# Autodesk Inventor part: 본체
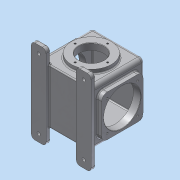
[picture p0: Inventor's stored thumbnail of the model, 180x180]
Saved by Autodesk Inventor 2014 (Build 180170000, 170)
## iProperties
Created: 2026-01
Part Number: 본체
Material: 알루미늄 6061
Document SubType Name: Modeling
Designer: dg
Mass: 2717.81 g
Surface Area: 2456.08 cm^2
Volume: 1002.88 cm^3
Density: 2.71 g/cm^3
Appearance: 알루미늄 - 평지
Author: dg
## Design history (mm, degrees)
sketch "스케치1"
  geometry: L1 (-71, 74)-(71, 74); L2 (71, 74)-(71, -74); L3 (71, -74)-(-71, -74); L4 (-71, -74)-(-71, 74); 3 further points
  constraints: 8 end point, 2 midpoint, 2 parallel, 1 horizontal, 1 horizontal alignment, 1 perpendicular, 1 vertical alignment
  dimensions: "d0" = 148 distance of L1.end L2.end; "d1" = 142 distance of L1.start L1.end
extrude "돌출1" new body sketch "스케치1" distance "d2" = 148; taper "d3" = 0 deg
fillet "모깎기1" dims "d7" = 10
fillet "모깎기2" dims "d8" = 10
feature "쉘2" dims "d82" = 7
sketch "스케치12"
  geometry: C1 r 54 at (0, 0); 1 further point
  constraints: 1 centre point, 1 coincident
  dimensions: "d79" = 108 diameter of C1
extrude "돌출8" join sketch "스케치12" distance "d80" = 11; taper "d81" = 0 deg
sketch "스케치13"
  geometry: L1 (0, 138)-(128, 138) reference; L2 (8, 130)-(120, 130); L3 (120, 130)-(120, 18); L4 (120, 18)-(8, 18); L5 (8, 18)-(8, 130); L6 (-21, 128)-(-21, 20) reference; 5 further points
  constraints: 8 end point, 4 midpoint, 2 parallel, 2 perpendicular, 1 horizontal, 1 horizontal alignment, 1 vertical alignment
  dimensions: "d83" = 112 distance of L2.start L2.end
extrude "돌출9" join sketch "스케치13" distance "d84" = 13; taper "d85" = 0 deg
fillet "모깎기9" dims "d86" = 15
sketch "스케치14"
  geometry: L1 (105, 130)-(23, 130) reference; L2 (8, 115)-(8, 33) reference; C1 r 50 at (64, 74); 3 further points
  constraints: 2 midpoint, 1 centre point, 1 horizontal alignment, 1 vertical alignment
  dimensions: "d87" = 100 diameter of C1
extrude "돌출10" cut sketch "스케치14" stored distance "d88" = 13; taper "d89" = 0 deg
fillet "모깎기10" dims "d90" = 3
hole "구멍5" diameter "d93" = 68; stored, may be unused: countersink angle "d97" = 90 deg, drill point angle "d99" = 118 deg; dims "d94" = 12, "d95" = 24, "d96" = 2, "d98" = 20, "d145" = 10, "d146" = 10
node "작업 평면2"
sketch "스케치15"
  geometry: L1 (122, 0)-(0, 0) reference; L2 (122, 128)-(122, 0) reference; L3 (0, 128)-(122, 128) reference; L4 (0, 0)-(0, 128) reference; L5 (-20, 178)-(20, 178); L6 (20, 178)-(20, -50); L7 (20, -50)-(-20, -50); L8 (-20, -50)-(-20, 178); L9 (102, 178)-(142, 178); L10 (142, 178)-(142, -50); L11 (142, -50)-(102, -50); L12 (102, -50)-(102, 178); 3 further points
  constraints: 16 end point, 4 parallel, 3 horizontal alignment, 2 horizontal, 2 midpoint, 2 perpendicular, 1 collinear
  dimensions: "d101" = 40 distance of L6.end L7.end; "d102" = 228 distance of L7.end L5.start; "d103" = 162 distance between parallel lines of L10 L8; "d104" = 81 distance from line of point (61, 138) L8
extrude "돌출11" join sketch "스케치15" distance "d105" = 12; taper "d106" = 0 deg
fillet "모깎기11" dims "d107" = 10
sketch "스케치16"
  geometry: L1 (-20, 168)-(-20, -40) reference; L2 (-20, -40)-(-20, 168) reference; 7 further points
  constraints: 2 horizontal alignment, 2 midpoint, 2 vertical alignment, 1 coincident
  dimensions: "d108" = 122 distance of point (122, -30) point (0, -30); "d109" = 61 horizontal distance of point (61, 138) point (0, -30); "d110" = 188 distance of point (0, -30) point (0, 158); "d111" = 94 vertical distance of point (-20, 64) point (0, 158)
hole "구멍6" sketch "스케치16" at (0, 158), (122, 158), (122, -30), (0, -30) diameter "d112" = 9; stored, may be unused: countersink angle "d116" = 90 deg, drill point angle "d118" = 118 deg; dims "d113" = 12, "d114" = 24, "d115" = 2, "d117" = 15
fillet "모깎기12" dims "d119" = 3
fillet "모깎기13" dims "d120" = 3
fillet "모깎기14" dims "d121" = 3
fillet "모깎기15" dims "d122" = 3
sketch "스케치17"
  geometry: C1 r 34 at (0, 0) reference; 1 further point
  constraints: 1 vertical alignment
  dimensions: "d123" = 44 distance of point (0, 44) C1.centre
hole "구멍7" sketch "스케치17" at (0, 44) diameter "d124" = 4.917; stored, may be unused: countersink angle "d128" = 90 deg, drill point angle "d130" = 118 deg; dims "d125" = 12, "d126" = 24, "d127" = 2, "d129" = 14
sketch "스케치18"
  geometry: A1 r 15 centre (105, 115) between (120, 115) and (105, 130) reference; A2 r 15 centre (23, 115) between (23, 130) and (8, 115) reference; A3 r 15 centre (23, 33) between (8, 33) and (23, 18) reference; A4 r 15 centre (105, 33) between (105, 18) and (120, 33) reference; 5 further points
  constraints: 4 coincident
hole "구멍8" sketch "스케치18" at (23, 115), (105, 115), (105, 33), (23, 33) diameter "d135" = 4.917; stored, may be unused: countersink angle "d139" = 90 deg, drill point angle "d141" = 118 deg; dims "d136" = 12, "d137" = 24, "d138" = 2, "d140" = 14
chamfer "모따기2" distance "d142" = 1; stored, may be unused: second distance "d143" = 2, angle "d144" = 45 deg
sketch "스케치19"
  geometry: L1 (122, 128)-(122, 0) reference; L2 (122, 138)-(0, 138) reference; 4 further points
  constraints: 2 midpoint, 1 horizontal alignment, 1 vertical alignment, 1 other
feature "엠보싱2" sketch "스케치19" dims "d0" = 148, "d1" = 142, "d147" = 0.5, "d148" = 0
node "솔리드1"
mirror "대칭3"
pattern_circular "원형 패턴2" dims angle "d132" = 360 deg
mirror "대칭4"
node "투영된 루프3"
other parameters: "d100" = -156
